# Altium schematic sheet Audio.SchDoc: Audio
size A4; DocumentNumber: 5; Revision: D.1(PCB.SCH); SheetNumber: 5; SheetTotal: 7
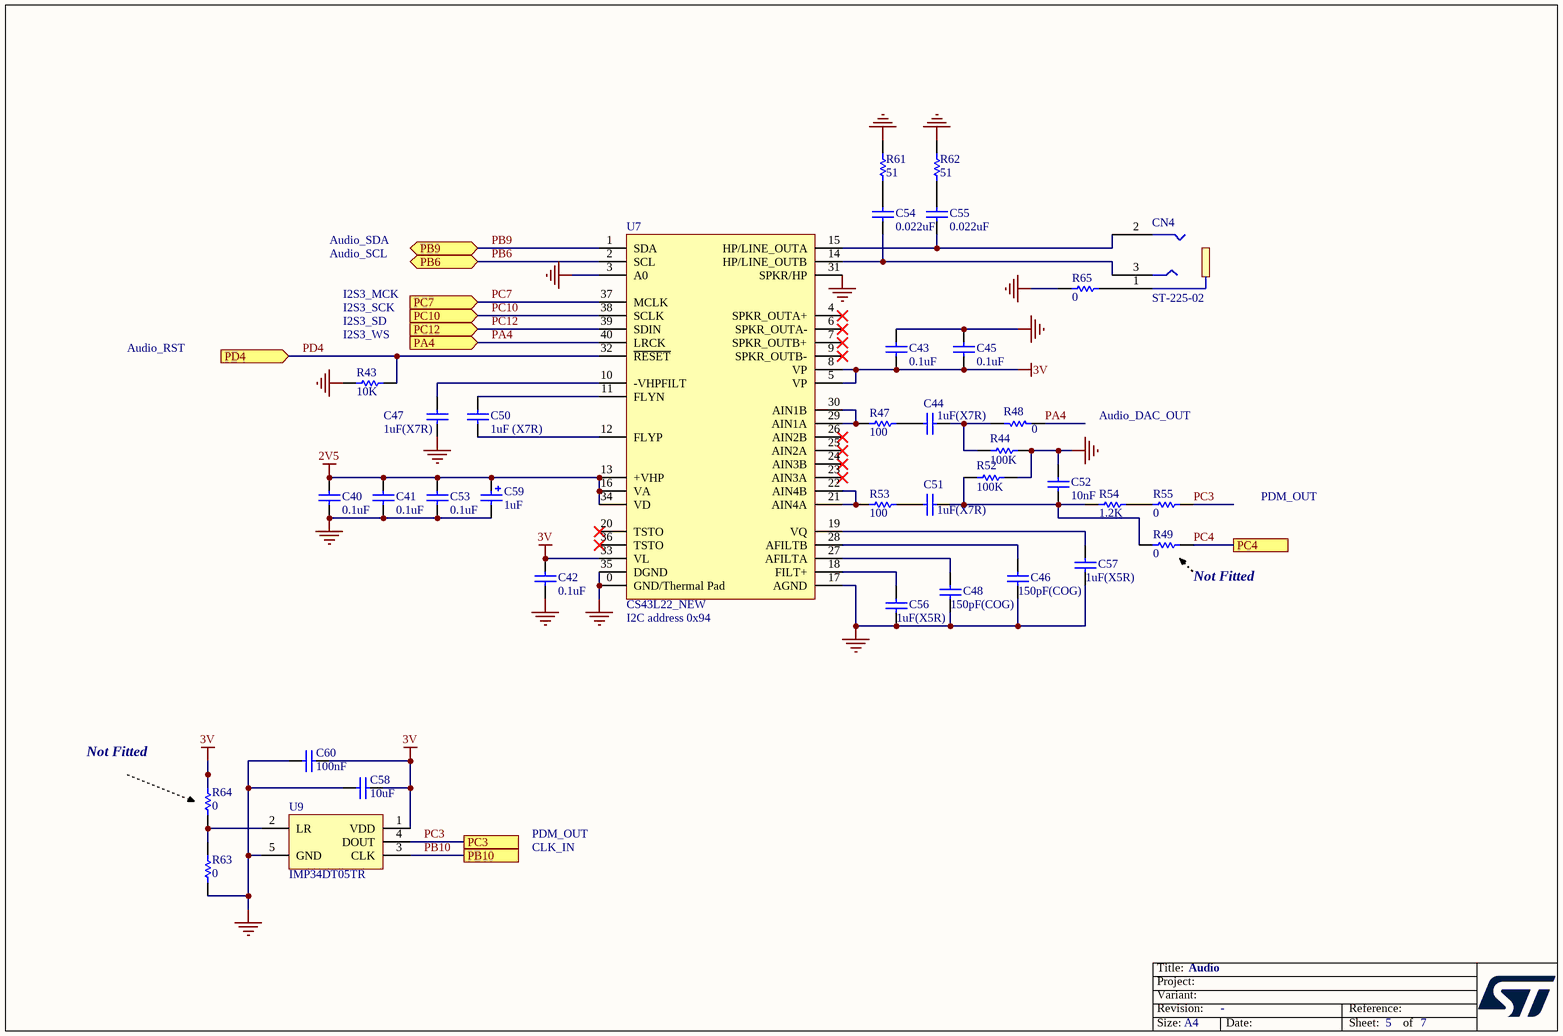
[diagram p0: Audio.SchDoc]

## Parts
C40  0.1uF  [0402C]
C41  0.1uF  [0402C]
C42  0.1uF  [0402C]
C43  0.1uF  [0402C]
C44  1uF(X7R)  [0603C]
C45  0.1uF  [0402C]
C46  150pF(COG)  [0603C]
C47  1uF(X7R)  [0603C]
C48  150pF(COG)  [0603C]
C50  1uF (X7R)  [0603C]
C51  1uF(X7R)  [0603C]
C52  10nF  [0603C]
C53  0.1uF  [0402C]
C54  0.022uF  [0603C]
C55  0.022uF  [0603C]
C56  1uF(X5R)  [0603C]
C57  1uF(X5R)  [0603C]
C58  10uF  [0603C]
C59  1uF  [CASE-A]
C60  100nF  [0402C]
CN4  ST-225-02  [PCBCOMPONENT_1$2F$2_new_]
R43  10K  [0402R]
R44  100K  [0402R]
R47  100  [0402R]
R48  0  [0603R]
R49  0  [0603R]
R52  100K  [0402R]
R53  100  [0402R]
R54  1.2K  [0603R]
R55  0  [0603R]
R61  51  [0603R]
R62  51  [0603R]
R63  0  [0402R]
R64  0  [0402R]
R65  0  [0603R]
U7  CS43L22_NEW  [QFN40(6_6)]
U9  IMP34DT05TR  [MIC_HCLGA_3X4X1_4LD_t]

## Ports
PA4 (in), PB6 (bidir), PB9 (bidir), PB10, PC3, PC4, PC7 (in), PC10 (in), PC12 (in), PD4 (in)

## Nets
2V5: C40.2 C41.2 C53.2 C59.1 U7.13(+VHP) U7.16(VA) U7.34(VD)
3V: C42.2 C43.2 C45.2 C58.2 C60.2 R64.2 U7.5(VP) U7.8(VP) U7.33(VL) U9.1(VDD)
GND: C40.1 C41.1 C42.1 C43.1 C45.1 C46.1 C47.2 C48.1 C52.2 C53.1 C56.1 C57.1 C58.1 C59.2 C60.1 R43.2 R44.2 R52.2 R61.1 R62.1 R63.1 R65.2 U7.0(GND/Thermal_Pad) U7.3(A0) U7.17(AGND) U7.31(SPKR/HP) U7.35(DGND) U9.5(GND)
PA4: R48.2 U7.40(LRCK) ; port PA4
PB6: U7.2(SCL) ; port PB6
PB9: U7.1(SDA) ; port PB9
PB10: U9.3(CLK) ; port PB10
PC3: R55.1 U9.4(DOUT) ; port PC3
PC4: R49.1 ; port PC4
PC7: U7.37(MCLK) ; port PC7
PC10: U7.38(SCLK) ; port PC10
PC12: U7.39(SDIN) ; port PC12
PD4: R43.1 U7.32(~{RESET}) ; port PD4
NetC44_1: C44.1 R47.1
NetC44_2: C44.2 R44.1 R48.1
NetC46_2: C46.2 U7.28(AFILTB)
NetC47_1: C47.1 U7.10(-VHPFILT)
NetC48_2: C48.2 U7.27(AFILTA)
NetC50_1: C50.1 U7.12(FLYP)
NetC50_2: C50.2 U7.11(FLYN)
NetC51_1: C51.1 R53.1
NetC51_2: C51.2 C52.1 R49.2 R52.1 R54.1
NetC54_1: C54.1 R61.2
NetC54_2: C54.2 CN4.3 U7.14(HP/LINE_OUTB)
NetC55_1: C55.1 R62.2
NetC55_2: C55.2 CN4.2 U7.15(HP/LINE_OUTA)
NetC56_2: C56.2 U7.18(FILT+)
NetC57_2: C57.2 U7.19(VQ)
NetCN4_1: CN4.1 R65.1
NetR47_2: R47.2 U7.29(AIN1A) U7.30(AIN1B)
NetR53_2: R53.2 U7.21(AIN4A) U7.22(AIN4B)
NetR54_2: R54.2 R55.2
NetR63_2: R63.2 R64.1 U9.2(LR)

Not connected (* = marked no-connect by the designer): U7 4(SPKR_OUTA+)* 6(SPKR_OUTA-)* 7(SPKR_OUTB+)* 9(SPKR_OUTB-)* 20(TSTO)* 23(AIN3A)* 24(AIN3B)* 25(AIN2A)* 26(AIN2B)* 36(TSTO)*

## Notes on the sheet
- Audio_SDA
- Audio_SCL
- I2S3_MCK
- I2S3_SCK
- Audio_RST
- (near R43) I2S3_WS
- I2S3_SD
- Audio_DAC_OUT
- PDM_OUT
- (near R49) Not Fitted
- (near U7) I2C address 0x94
- Not Fitted
- CLK_IN

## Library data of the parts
C40-C43 C53 = CAP: Capacitor; Manuf_1: YAGEO; Manuf_Part_1: CC0402KRX7R7BB104; Value: 100nF
C44 C47 C50 C51 C56 C57 = CAP: Capacitor; Manuf_Part_1: CC0603KRX5R7BB105; Manuf_1: YAGEO
C45 = CAP: Capacitor; Manuf_Part_1: CC0402KRX7R7BB104; Manuf_1: YAGEO; Value: 100nF
C46 C48 = CAP: Capacitor; Manuf_Part_1: CC0603JRNPO9BN151; Manuf_1: YAGEO
C52 = CAP: Capacitor; Manuf_Part_1: CC0603KRX7R9BB103; Manuf_1: YAGEO
C54 C55 = CAP: Capacitor; Manuf_Part_1: CC0603KRX7R9BB223; Manuf_1: YAGEO
C58 = CAP: Capacitor; Manuf_Part_1: CC0603KRX5R5BB106; Manuf_1: YAGEO
C59 = Cap Pol1: Polarized Capacitor (Radial); Manuf_Part_1: TAJA105K016R; Manuf_1: AVX
C60 = CAP: Capacitor; Manuf_Part_1: CC0402KRX7R7BB104; Manuf_1: YAGEO
CN4 = ST-225-02_: Connector Jack 35mm; Manuf_1: XIEJIA Electronics
R43 = res1: Resistor; Manuf_Part_1: RC0402FR-0710KL; Manuf_1: YAGEO
R44 R52 = res1: Resistor; Manuf_Part_1: RC0402FR-07100KL; Manuf_1: YAGEO
R47 R53 = res1: Resistor; Manuf_Part_1: RC0402FR-07100RL; Manuf_1: YAGEO
R48 R55 R65 = res1: Resistor; Manuf_Part_1: RC0603JR-070RL; Manuf_1: YAGEO
R49 = res1: Resistor; Manuf_Part_1: RC0603JR-070RL; Manuf_1: YAGEO; Fitted: NO
R54 = res1: Resistor; Manuf_Part_1: RC0603FR-071K2L; Manuf_1: YAGEO
R61 R62 = res1: Resistor; Manuf_Part_1: RC0603FR-0751RL; Manuf_1: YAGEO
R63 = res1: Resistor; Manuf_part_1: RC0402JR-070RL; Manuf_1: YAGEO
R64 = res1: Resistor; Fitted: NO
U7 = CS43L22_NEW: Low Power, Stereo DAC w/Headphone & Speaker Amps; Manuf_1: Cirrus; Manuf_Part_1: CS43L22-CNZ
U9 = IMP34DT05TR: MEMS audio sensor omnidirectional digital microphone for industrial applications; Manuf_1: STM; Provided: ST; Ref St: 9177995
